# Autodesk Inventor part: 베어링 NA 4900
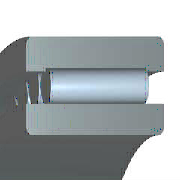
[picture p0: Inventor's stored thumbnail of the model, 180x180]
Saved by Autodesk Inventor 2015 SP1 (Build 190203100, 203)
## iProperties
Created: 2014-07
Part Number: 베어링 NA 4900
Material: Steel, Mild
Description: 니들 롤러 베어링 - 경계 치수 및 공차
Document SubType Name: Modeling
Standard: KS B 2029
Designer: KYOUNG IL JANG
Standards Organization: KS
Language: ko-KR
Size Designation: NA 4900 - 10 x 22 x 13
Categories: <MemberInstance><Categories><Category DisplayName="샤프트 부품" InternalName="7f7aeb1f-a693-4053-b835-cee3144e0d98" Mnemonic="SHFT"><Category DisplayName="베어링" Inter
Density: 7.86 g/cm^3
Appearance: Metal-Steel
Mass: 23.8213 g
Surface Area: 38.613 cm^2
Volume: 3.0307 cm^3
Company: 한국ATC센터
IsCustomPart: 0
Author: KYOUNG IL JANG
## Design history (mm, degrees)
sketch "스케치"
  geometry: L1 (1.857, 9)-(11.143, 9); L2 (11.143, 9)-(11.143, 7); L3 (13, 7)-(0, 7); L4 (1.857, 7)-(1.857, 9); L5 (1.857, 8)-(11.143, 8); L6 (6.5, 8)-(6.5, 7); L7 (0, 5)-(13, 5); L8 (0, 11)-(13, 11); L9 (13, 5)-(13, 7); L10 (13, 8.8)-(13, 11); L11 (1.857, 8.8)-(0, 8.8); L12 (11.143, 8.8)-(13, 8.8); L13 (-6, 0)-(36, 0) reference; L14 (0, -1.9)-(0, 14.9) reference
  constraints: 24 end point, 8 point on line, 3 midpoint, 3 parallel, 3 perpendicular, 2 symmetric about line, 1 horizontal, 1 other
  dimensions: "d6" = 10 diameter of L7 L13 (= WD); "d7" = 14 diameter of L3 L13 (= KID1); "d8" = 22 diameter of L8 L13 (= BD); "d9" = 16 diameter of L6.start L13 (= 0.5 x WD + 0.5 x BD); "d10" = 17.6 diameter of L12 L13 (= 0.9 x BD + 0.9 x WD - 0.8 x KID1); "d11" = 18 diameter of L1 L13 (= BD + WD - KID1); "d12" = 1.85714 distance between parallel lines of L14 L4 (= 0.142857 x KB); "d13" = 13 distance between parallel lines of L14 L9 (= KB); "d14" = 11.14286 distance between parallel lines of L14 L2 (= 0.857143 x KB)
revolve "본체" stored, may be unused: angle "d17" = 90 deg
revolve "롤러" stored, may be unused: angle "d18" = 90 deg
pattern_circular "IDS_ARRAYROLLER[SIMPL:T]" dims angle "d2" = 360 deg
body "Solid1"
fillet "모깎기1" dims "d0" = 0.3 (= KRS)
other parameters: "WD" = 10 [user parameter; used in 6 equation terms], "BD" = 22 [user parameter; used in 6 equation terms], "KB" = 13 [user parameter; used in 3 equation terms], "KID1" = 14 [user parameter; used in 4 equation terms], "KRS" = 0.3 [user parameter; used in 1 equation term], "d3" = 0, "d4" = 0, "d5" = 0, "d15" = 0, "d16" = 0, "BC0" = 9150000 [user parameter], "WR" = 5 (= 0.5 x WD) [user parameter], "BBA" = 0 [user parameter], "BC" = 8150000 [user parameter], "BR" = 11 (= 0.5 x BD) [user parameter]
